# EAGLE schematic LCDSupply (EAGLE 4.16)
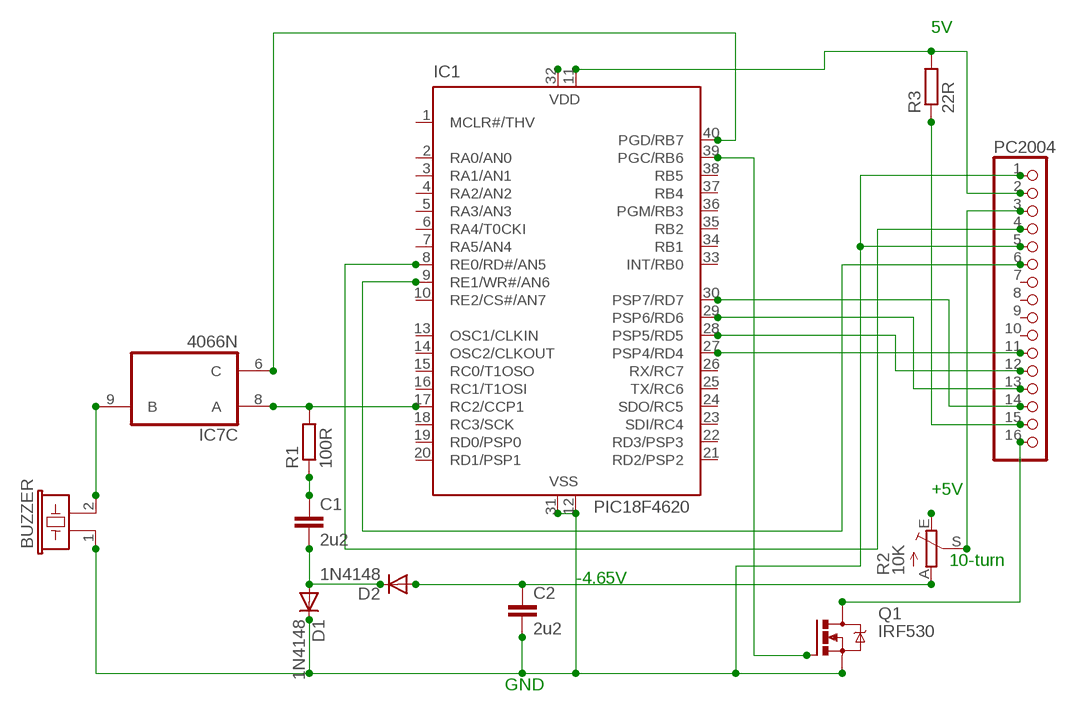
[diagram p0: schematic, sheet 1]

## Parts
BUZZER  B/C11L  [B/C11L]
C1  2u2  C-EU050-025X075  [C050-025X075]
C2  2u2  C-EU050-025X075  [C050-025X075]
D1  1N4148  [DO35-10]
D2  1N4148  [DO35-10]
IC1  PIC18F4620  PIC16F874P  [DIL40]
IC7  4066N  [DIL14]
PC2004  PINHD-1X16  [1X16]
Q1  IRF530  [TO220BV]
R1  100R  R-EU_0309/12  [0309/12]
R2  10K  TRIM_EU-ECP10P  [ECP10P]
R3  22R  R-EU_0309/12  [0309/12]

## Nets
N$2: IC1.17(RC2/CCP1) IC7.8(C:A) R1.2
N$3: BUZZER.2 IC7.9(C:B)
N$4: C1.1 R1.1
N$5: BUZZER.1 C2.2 D1.C IC1.12(VSS) IC1.31(VSS) PC2004.1 PC2004.5 Q1.S
N$6: PC2004.15 R3.1
N$7: C1.2 D1.A D2.C
N$9: IC1.40(PGD/RB7) IC7.6(C:C)
N$10: PC2004.16 Q1.D
N$11: IC1.32(VDD)
N$12: C2.1 D2.A R2.A
N$13: R2.E
N$14: IC1.39(PGC/RB6) Q1.G
N$15: PC2004.3 R2.S
N$16: IC1.11(VDD) PC2004.2 R3.2
N$20: IC1.30(PSP7/RD7) PC2004.14
N$21: IC1.29(PSP6/RD6) PC2004.13
N$22: IC1.28(PSP5/RD5) PC2004.12
N$23: IC1.27(PSP4/RD4) PC2004.11
N$28: IC1.8(RE0/RD#/AN5) PC2004.4
N$30: IC1.9(RE1/WR#/AN6) PC2004.6
Unconnected: IC1.1(MCLR#/THV) IC1.2(RA0/AN0) IC1.3(RA1/AN1) IC1.4(RA2/AN2) IC1.5(RA3/AN3) IC1.6(RA4/T0CKI) IC1.7(RA5/AN4) IC1.10(RE2/CS#/AN7) IC1.13(OSC1/CLKIN) IC1.14(OSC2/CLKOUT) IC1.15(RC0/T1OSO) IC1.16(RC1/T1OSI) IC1.18(RC3/SCK) IC1.19(RD0/PSP0) IC1.20(RD1/PSP1) IC1.21(RD2/PSP2) IC1.22(RD3/PSP3) IC1.23(SDI/RC4) IC1.24(SDO/RC5) IC1.25(TX/RC6) IC1.26(RX/RC7) IC1.33(INT/RB0) IC1.34(RB1) IC1.35(RB2) IC1.36(PGM/RB3) IC1.37(RB4) IC1.38(RB5) IC7.1(A:A) IC7.2(A:B) IC7.3(B:B) IC7.4(B:A) IC7.5(B:C) IC7.10(D:B) IC7.11(D:A) IC7.12(D:C) IC7.13(A:C) PC2004.7 PC2004.8 PC2004.9 PC2004.10

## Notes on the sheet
- 5V
- +5V
- 10-turn
- -4.65V
- GND

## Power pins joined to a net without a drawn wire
VDD: IC7.14(P:VDD)
VSS: IC7.7(P:VSS)

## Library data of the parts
BUZZER = buzzer:B/C11L: BUZZER
C1 C2 = rcl:C-EU: CAPACITOR, European symbol
D1 D2 = diode:1N4148: DIODE
IC1 = microchip:PIC16F87*: MICROCONTROLLER
IC7 = 40xx:4066: Quad bilateral ANALOG SWITCH
PC2004 = pinhead:PINHD-1X16: PIN HEADER
Q1 = transistor-power:IRF530: HEXFET Power MOSFET
R1 R3 = rcl:R-EU_: RESISTOR, European symbol
R2 = pot:TRIM_EU-: POTENTIOMETER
